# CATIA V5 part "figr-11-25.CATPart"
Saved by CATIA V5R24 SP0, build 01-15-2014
Part number: Part1
Bounding box of the stored display mesh (mm): x -89.703 to 75.958, y -127.286 to 108.862, z -26.487 to 19.815
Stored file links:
  D:\KAVITA\CATIA V5-6R2014 Project_ Kavita\CATIA V5-6R2014_partfiles\Partfiles\c11_catia_v5-6r2014_prt\figr-11-25.CATPart
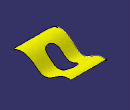
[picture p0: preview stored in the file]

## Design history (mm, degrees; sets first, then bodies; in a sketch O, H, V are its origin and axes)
Set1
  Extrude1: Element1 Sketch3, Lim1 86, Lim2 94, Direction yz-plane
  Sketch1 on xy-plane, origin (0, 0, 0), H (1, 0, 0), V (0, 1, 0)
    line L1 (64.3059, 108.8616) -> (75.9293, -106.0218)
    arc A1 centre (55.7837, -107.1115) radius 20.175 from (75.9293, -106.0218) to (55.7837, -127.2865) cw
    line L2 (55.7837, -127.2865) -> (-64.7868, -127.2865)
    arc A2 centre (-64.7868, -102.3613) radius 24.9252 from (-64.7868, -127.2865) to (-89.6873, -101.2501) cw
    line L3 (-89.6873, -101.2501) -> (-80.3115, 108.8616)
    line L4 (-80.3115, 108.8616) -> (64.3059, 108.8616)
    tangency: A1 L1, A2 L2, A2 L3, A1 L2
    horizontal: L2 H, L4 H
  Extrude2: Element1 Sketch1, Lim1 86, Lim2 94, Direction xy-plane
  Split1: ToCut Extrude1, Cutting Extrude2
  Sketch2 on xy-plane, origin (0, 0, 0), H (1, 0, 0), V (0, 1, 0)
    construction line L1 (-11.3849, 28.4134) -> (-11.3849, -36.9379)
    line L2 (12.8382, 28.4134) -> (12.8382, -36.9379)
    line L3 (-35.608, -36.9379) -> (-35.608, 28.4134)
    arc A1 centre (-11.3849, -36.9379) radius 24.2231 from (12.8382, -36.9379) to (-35.608, -36.9379) cw
    arc A2 centre (-11.3849, 28.4134) radius 24.2231 from (-35.608, 28.4134) to (12.8382, 28.4134) cw
    vertical: L1 V
    tangency: A1 L2, A2 L2, A1 L3, A2 L3
    parallelism: L1 L2
  Extrude3: Element1 Sketch2, Lim1 86, Lim2 94, Direction xy-plane
  Split2: ToCut Split1, Cutting Extrude3
  Boundary1: Boundary edge of Split2, Support Split2
Body1 (main body)
  Sketch3 on yz-plane, origin (0, 0, 0), H (0, 1, 0), V (0, 0, 1)
    spline S1 through (-130.9721, 0) (-85.5087, 19.8151) (-38.0512, 0) (0, -25.6483) (60.0541, -1.7202) (134.7951, -4.3868)
    point P1 (-130.9721, 0)
    point P2 (-38.0512, 0)
    point P3 (0, -25.6483)
    coincidence: P1 H, P2 H, P3 V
